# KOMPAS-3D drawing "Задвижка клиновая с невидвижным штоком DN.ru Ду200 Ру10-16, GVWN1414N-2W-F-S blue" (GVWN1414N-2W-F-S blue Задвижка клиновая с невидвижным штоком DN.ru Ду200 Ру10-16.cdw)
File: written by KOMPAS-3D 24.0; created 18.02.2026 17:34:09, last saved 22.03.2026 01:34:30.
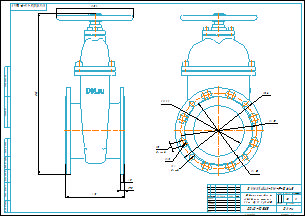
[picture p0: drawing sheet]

Document properties: Автор: R2D2; Форматы листов документа: A2; Полное имя файла: GVWN1414N-2W-F-S blue Задвижка клиновая с невидвижным штоком DN.ru Ду200 Ру10-16.m3d; Масса: 38; Наименование: Задвижка клиновая с невидвижным штоком DN.ru Ду200 Ру10-16; Количество листов документа: 1; Примечание: D040-10585

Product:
- Part/product: Задвижка клиновая с невидвижным штоком DN.ru Ду200 Ру10-16  | designation GVWN1414N-2W-F-S blue
    Масса: 38
    Раздел спецификации: Прочие изделия
    Примечание: D040-10585

Views: Вид 1, Спереди, Проекционный вид 2
Referenced files in E:\Работа\Зайцев\GVWN1414N-2W-F-S blue Задвижка клиновая с невидвижным штоком DN.ru Ду40-300 Ру10-16\DN200\: GVWN1414N-2W-F-S blue Задвижка клиновая с невидвижным штоком DN.ru Ду200 Ру10-16.m3d
Referenced files in E:\Работа\Зайцев\Для компаса\: чертеж DN.ru А3.cdt
Referenced files in E:\Работа\Зайцев\!готово\GVWN1414N-2W-F-S blue Задвижка клиновая с невидвижным штоком DN.ru Ду40-300 Ру10-16\DN200\: GVWN1414N-2W-F-S blue Задвижка клиновая с невидвижным штоком DN.ru Ду200 Ру10-16.m3d
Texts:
  GVWN1414N-2W-F-S blue
  чертеж DN.ru А3.cdt
  Задвижка клиновая с
  невидвижным штоком
  DN.ru Ду200 Ру10-16
  Задвижка клиновая с невидвижным штоком DN.ru Ду200 Ру10-16
  GVWN1414N-2W-F-S blue Задвижка клиновая с невидвижным штоком DN.ru Ду200 Ру10-16
Dimensions and other numbers on the sheet: 0; 3; 2; 4; 230; 17,5; 2,5; 630; 300; 340; 295; 265; 200; 23; 19; 8 пазов; 22; 8 отв.; 1:2; 1; 38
